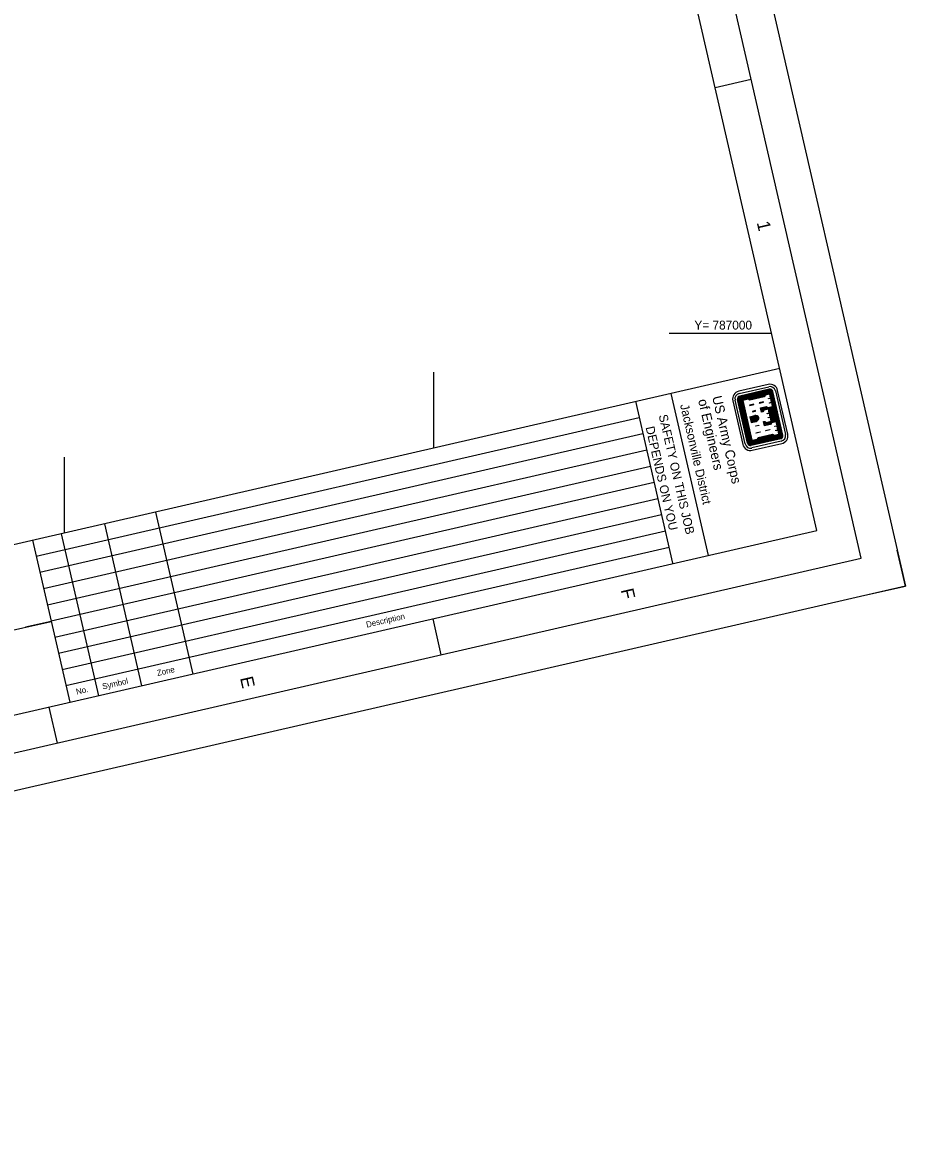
# Model space of a CAD drawing. Extents: x 604840 to 609139, y 785896 to 790946.
# Drawn here: x 607943 to 609139, y 785896 to 787421 of the extents above; entities that cross this region are included whole.
import ezdxf

# ---------------------------------------------------------------- set-up
doc = ezdxf.new("R2010")
doc.units = 0
for name, color, linetype in [('G-ANNO-NPLT', 7, 'Continuous'), ('G-ANNO-TEXT-LOGO', 7, 'Continuous'), ('G-ANNO-TEXT-TTLB', 7, 'Continuous'), ('G-ANNO-TTLB', 7, 'Continuous'), ('V-TOPO-COOR-STAT', 7, 'Continuous')]:
    doc.layers.add(name, color=color, linetype=linetype)

msp = doc.modelspace()

# ---------------------------------------------------------------- linework, layer by layer
at = {"layer": 'G-ANNO-NPLT'}
msp.add_lwpolyline([(608153.4, 790946.1), (609138.7, 786657.8), (605825.1, 785896.5), (604839.8, 790184.7)], close=True, dxfattribs=at)
msp.add_lwpolyline([(609090, 786646.6), (609138.7, 786657.8), (609127.5, 786706.5)], dxfattribs=at)
at = {"layer": 'G-ANNO-TEXT-LOGO'}
for p, q in [((608952.8, 786930.8), (608912.8, 786921.6)), ((608913.5, 786918.5), (608953.5, 786927.6)), ((608954.3, 786924.2), (608914.3, 786915)), ((608954.5, 786923.3), (608914.5, 786914.2)), ((608954.6, 786922.6), (608914.7, 786913.4)), ((608954.8, 786921.7), (608914.9, 786912.5)), ((608955, 786920.8), (608915.1, 786911.6)), ((608955.2, 786919.9), (608915.6, 786910.8)), ((608955.4, 786919.2), (608916.6, 786910.2)), ((608947.1, 786916.5), (608926.6, 786911.8)), ((608969.4, 786861.2), (608955.7, 786920.5)), ((608970.2, 786861.4), (608956.6, 786920.7)), ((608971, 786861.6), (608957.4, 786920.8)), ((608971.9, 786861.8), (608958.3, 786921)), ((608972.8, 786862), (608959.2, 786921.2)), ((608962.5, 786922), (608976.1, 786862.7)), ((608979.2, 786863.5), (608965.6, 786922.7)), ((608904.7, 786908.7), (608918.3, 786849.5)), ((608921.5, 786850.2), (608907.9, 786909.5)), ((608924.9, 786851), (608911.3, 786910.2)), ((608925.7, 786851.2), (608912.1, 786910.4)), ((608926.6, 786851.4), (608913, 786910.6)), ((608927.4, 786851.6), (608913.8, 786910.8)), ((608928.2, 786851.8), (608914.6, 786911)), ((608929, 786852.3), (608915.6, 786910.8)), ((608929.7, 786853.3), (608916.6, 786910.2)), ((608946.4, 786915.4), (608927.8, 786911.2)), ((608928, 786887), (608934.6, 786888.5)), ((608928, 786887), (608929.8, 786879.2)), ((608928.2, 786886.2), (608934.7, 786887.7)), ((608928.4, 786885.3), (608934.9, 786886.8)), ((608928.6, 786884.5), (608935.1, 786886)), ((608954.6, 786898.5), (608958.8, 786880.4)), ((608955.5, 786898.8), (608959.7, 786880.6)), ((608956.3, 786898.9), (608960.4, 786880.8)), ((608957.2, 786899.1), (608961.3, 786881)), ((608958, 786899.3), (608962.2, 786881.2)), ((608958.8, 786899.5), (608963, 786881.4)), ((608959.7, 786899.7), (608963.9, 786881.6)), ((608928.8, 786883.7), (608935.3, 786885.2)), ((608929.1, 786882.5), (608935.6, 786884)), ((608929.2, 786881.7), (608935.8, 786883.2)), ((608929.4, 786880.9), (608936, 786882.4)), ((608929.6, 786880), (608936.2, 786881.5)), ((608929.8, 786879.2), (608936.4, 786880.7)), ((608968.9, 786860.6), (608928.9, 786851.4)), ((608968.7, 786861.5), (608929, 786852.3)), ((608969.1, 786859.7), (608929.1, 786850.5)), ((608969.3, 786858.9), (608929.3, 786849.7)), ((608969.5, 786858), (608929.5, 786848.9)), ((608968.5, 786862.2), (608929.7, 786853.3)), ((608969.7, 786857.2), (608929.7, 786848)), ((608959.8, 786860.9), (608939.5, 786856.3)), ((608958.8, 786861.6), (608940.2, 786857.4)), ((608970.4, 786853.9), (608930.5, 786844.7)), ((608931.2, 786841.5), (608971.2, 786850.6))]:
    msp.add_line(p, q, dxfattribs=at)
for points in [[(608955.6, 786918.5), (608947.9, 786916.7), (608946.6, 786914.7), (608928, 786910.4), (608925.9, 786911.6), (608917.4, 786909.7), (608930.1, 786854.1), (608938.6, 786856.1), (608940, 786858.2), (608958.6, 786862.5), (608960.6, 786861.1), (608968.3, 786862.9), (608966.7, 786870.2), (608965.4, 786875.9), (608964.2, 786881.1), (608956.5, 786879.4), (608955.2, 786877.1), (608948.4, 786875.6), (608947.5, 786879.7), (608948.1, 786879.8), (608950.3, 786878.5), (608957.9, 786880.2), (608956.2, 786887.5), (608954.9, 786893.2), (608953.7, 786898.3), (608946.1, 786896.6), (608944.8, 786894.4), (608944.1, 786894.3), (608943.2, 786898.4), (608950, 786899.9), (608952, 786898.6), (608959.7, 786900.3), (608958.1, 786907.7), (608956.8, 786913.3), (608955.6, 786918.5)], [(608954.9, 786917.5), (608948.5, 786916), (608947.1, 786913.9), (608927.8, 786909.4), (608925.6, 786910.8), (608918.4, 786909.1), (608930.8, 786855.1), (608938.1, 786856.8), (608939.4, 786859), (608958.7, 786863.5), (608960.9, 786862), (608967.3, 786863.5), (608966.1, 786868.8), (608963.1, 786868.1), (608962.9, 786868.6), (608966, 786869.2), (608964.8, 786874.4), (608961.8, 786873.7), (608961.7, 786874.1), (608964.7, 786874.8), (608963.5, 786880.1), (608957.1, 786878.6), (608955.7, 786876.4), (608947.8, 786874.6), (608946.5, 786880.3), (608948.4, 786880.7), (608950.5, 786879.3), (608956.9, 786880.8), (608955.7, 786886.1), (608952.7, 786885.4), (608952.6, 786885.8), (608955.6, 786886.5), (608954.4, 786891.7), (608951.4, 786891), (608951.3, 786891.5), (608954.3, 786892.2), (608953.1, 786897.4), (608946.7, 786895.9), (608945.4, 786893.8), (608943.5, 786893.3), (608942.2, 786899), (608950.1, 786900.8), (608952.3, 786899.4), (608958.7, 786900.9), (608957.5, 786906.1), (608954.5, 786905.4), (608954.4, 786905.9), (608957.4, 786906.6), (608956.2, 786911.8), (608953.2, 786911.1), (608953.1, 786911.5), (608956.1, 786912.2), (608954.9, 786917.5)], [(608933.3, 786904.1), (608927.6, 786902.8), (608927.7, 786902.2), (608933.5, 786903.5), (608933.3, 786904.1)], [(608946.3, 786907.1), (608940.6, 786905.8), (608940.8, 786905.2), (608946.4, 786906.5), (608946.3, 786907.1)], [(608935.4, 786895.2), (608931.4, 786894.2), (608931.5, 786893.8), (608935.5, 786894.7), (608935.4, 786895.2)], [(608950.4, 786898.6), (608949.8, 786899), (608944.2, 786897.7), (608944.7, 786895.9), (608945.6, 786897.4), (608950.5, 786898.5)], [(608940, 786875.1), (608936, 786874.2), (608935.9, 786874.6), (608939.9, 786875.6), (608940, 786875.1)], [(608955, 786878.5), (608954.6, 786877.9), (608949.1, 786876.7), (608948.7, 786878.4), (608950.2, 786877.5), (608955.1, 786878.6)], [(608942, 786866.2), (608936.3, 786864.9), (608936.2, 786865.4), (608941.9, 786866.7), (608942, 786866.2)], [(608955, 786869.2), (608949.4, 786867.9), (608949.2, 786868.4), (608954.9, 786869.7), (608955, 786869.2)]]:
    msp.add_lwpolyline(points, dxfattribs=at)
for centre, major_axis, start_param, end_param in [((608955.2, 786920.3), (2.4, -10.4), 1.57078, 3.141576), ((608915.2, 786911.1), (-2.4, 10.4), 6.28317, 7.853966), ((608915.2, 786911.1), (-1.68, 7.3), 6.28317, 7.853966), ((608955.2, 786920.3), (1.68, -7.3), 1.57078, 3.141576), ((608955.2, 786920.3), (0.9, -3.92), 1.57078, 3.141576), ((608955.2, 786920.3), (0.71, -3.07), 1.57078, 3.141576), ((608955.2, 786920.3), (0.51, -2.22), 1.57078, 3.141576), ((608955.2, 786920.3), (0.32, -1.38), 1.57078, 3.141576), ((608955.2, 786920.3), (0.122, -0.532), 1.57078, 3.141576), ((608915.2, 786911.1), (-0.9, 3.92), 6.28317, 7.853966), ((608915.2, 786911.1), (-0.71, 3.07), 6.28317, 7.853966), ((608915.2, 786911.1), (-0.51, 2.22), 6.28317, 7.853966), ((608915.2, 786911.1), (-0.32, 1.38), 6.28317, 7.853966), ((608915.2, 786911.1), (-0.122, 0.532), 6.28317, 7.853966), ((608935.4, 786883.1), (-1.24, 5.41), 4.985832, 6.214359), ((608935.4, 786883.1), (-1.05, 4.57), 4.947465, 6.21436), ((608935.4, 786883.1), (-0.85, 3.72), 4.947465, 6.21436), ((608935.4, 786883.1), (-0.66, 2.87), 4.947465, 6.21436), ((608934.7, 786886), (0.47, -2.03), 0.068794, 1.335689), ((608934.7, 786886), (0.66, -2.87), 0.068794, 1.335689), ((608934.7, 786886), (0.85, -3.72), 0.068795, 1.335689), ((608934.7, 786886), (1.05, -4.57), 0.068795, 1.335689), ((608934.7, 786886), (1.24, -5.41), 0.068795, 1.29842), ((608935.4, 786883.1), (-0.47, 2.03), 4.947465, 6.214359), ((608968.8, 786861.1), (0.122, -0.532), 6.283169, 7.853965), ((608968.8, 786861.1), (0.32, -1.38), 6.283169, 7.853965), ((608968.8, 786861.1), (0.51, -2.22), 6.283169, 7.853965), ((608968.8, 786861.1), (0.71, -3.07), 6.283169, 7.853965), ((608968.8, 786861.1), (0.9, -3.92), 6.283169, 7.853965), ((608968.8, 786861.1), (1.68, -7.3), 6.28317, 7.853966), ((608968.8, 786861.1), (2.4, -10.4), 6.283169, 7.853965), ((608928.8, 786851.9), (2.4, -10.4), 4.712373, 6.28317), ((608928.8, 786851.9), (-1.68, 7.3), 1.570781, 3.141577), ((608928.8, 786851.9), (0.9, -3.92), 4.712373, 6.28317), ((608928.8, 786851.9), (0.71, -3.07), 4.712373, 6.28317), ((608928.8, 786851.9), (0.51, -2.22), 4.712373, 6.28317), ((608928.8, 786851.9), (0.32, -1.38), 4.712373, 6.28317), ((608928.8, 786851.9), (0.122, -0.532), 4.712373, 6.28317)]:
    msp.add_ellipse(centre, major_axis=major_axis, ratio=0.99964, start_param=start_param, end_param=end_param, dxfattribs=at)
at = {"layer": 'G-ANNO-TTLB'}
for p, q in [((608929.8, 787343.5), (608881.1, 787332.3)), ((608968.4, 786952.2), (605849.7, 786235.6)), ((608821.1, 786918.3), (608871.4, 786699)), ((608773, 786907.9), (608823.4, 786688.6)), ((608778.2, 786885.6), (607961.5, 786697.9)), ((608783.2, 786863.6), (607966.6, 786676)), ((608788.3, 786841.7), (607971.6, 786654.1)), ((608793.3, 786819.8), (607976.7, 786632.1)), ((608798.3, 786797.8), (607981.7, 786610.2)), ((608803.4, 786775.9), (607986.7, 786588.3)), ((608808.4, 786754), (607991.8, 786566.4)), ((608123.2, 786758), (608173.6, 786538.7)), ((608053.9, 786742), (608104.3, 786522.7)), ((607956.6, 786719.7), (608006.9, 786500.4)), ((607995.4, 786728.6), (608045.7, 786509.3)), ((608813.5, 786732.1), (607996.8, 786544.4)), ((608818.5, 786710.1), (608001.9, 786522.5)), ((608510.1, 786564.7), (608498.9, 786613.4)), ((607143.9, 786418.2), (607981.7, 786610)), ((607981.7, 786610), (607947.2, 786602.1)), ((607990.3, 786445.3), (607979.1, 786494))]:
    msp.add_line(p, q, dxfattribs=at)
for points in [[(604899.7, 790147.2), (605862.6, 785956.4), (609078.8, 786695.3), (608115.9, 790886.1)], [(609018.8, 786732.9), (608095.1, 790753.1), (604976.4, 790036.5), (605900.1, 786016.3)]]:
    msp.add_lwpolyline(points, close=True, dxfattribs=at)
at = {"layer": 'V-TOPO-COOR-STAT'}
for p, q in [((608818.9, 787000), (608957.5, 787000)), ((608500, 786844.6), (608500, 786947.2)), ((608000, 786729.7), (608000, 786832.3))]:
    msp.add_line(p, q, dxfattribs=at)

# ---------------------------------------------------------------- texts
at = {"layer": 'G-ANNO-TEXT-TTLB'}
for s, height, rotation, p in [('Jacksonville District', 11.9, 282.9401, (608833.4, 786902.7)), ('of Engineers', 13.086, 282.9401, (608857.8, 786909.4)), ('US Army Corps', 13.086, 282.9401, (608876.8, 786913.7)), ('SAFETY ON THIS JOB', 11.9, 282.9401, (608804.4, 786888.7)), ('DEPENDS ON YOU', 11.9, 282.9401, (608786.7, 786872.6)), ('Description', 8, 12.9401, (608409.3, 786601.4)), ('Zone', 8, 12.9401, (608126, 786536)), ('No.', 8, 12.9401, (608016.5, 786510.7)), ('Symbol', 8, 12.9401, (608051.9, 786517.8))]:
    msp.add_text(s, height=height, rotation=rotation, dxfattribs=at).set_placement(p)
at = {"layer": 'G-ANNO-TTLB'}
for s, p in [('1', (608937.2, 787149.8)), ('F', (608752.8, 786652.5)), ('E', (608237.5, 786533.3))]:
    msp.add_text(s, height=17.5, rotation=282.9401, dxfattribs=at).set_placement(p)
at = {"layer": 'V-TOPO-COOR-STAT'}
msp.add_text('Y= 787000', height=12, dxfattribs=at).set_placement((608852.8, 787005))

doc.saveas('drawing.dxf')
